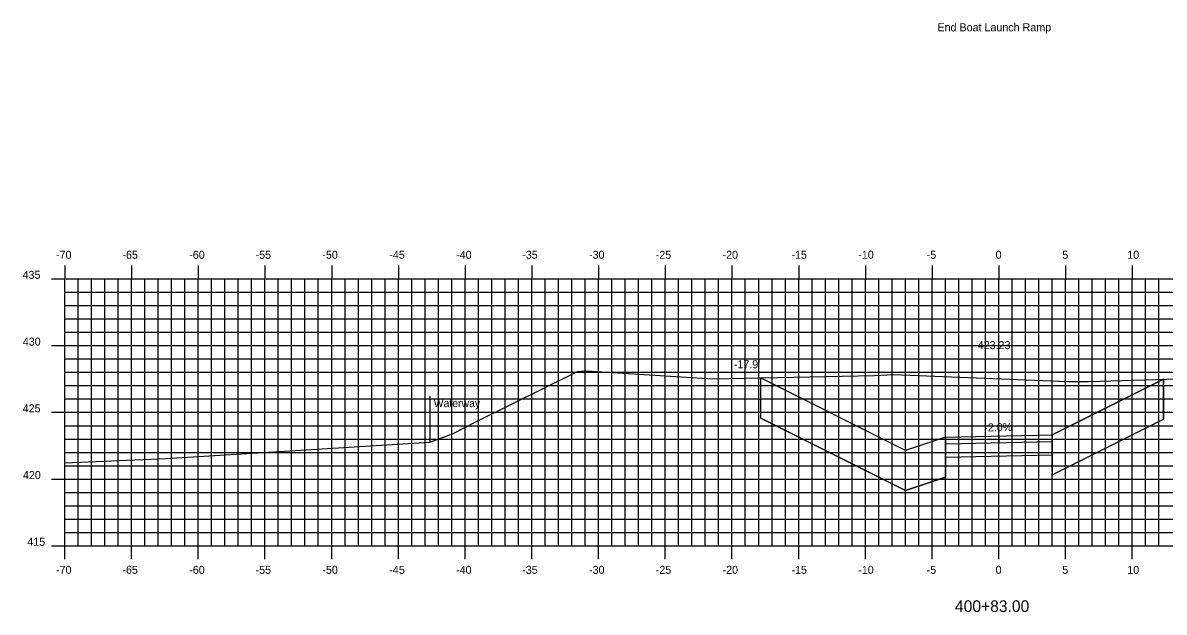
# Model space of a CAD drawing. Extents: x -161 to 764, y 111 to 210.
# Drawn here: x 606.1 to 691.6, y 120.8 to 164.9 of the extents above; entities that cross this region are included whole.
import ezdxf

# ---------------------------------------------------------------- set-up
doc = ezdxf.new("R2010")
doc.units = 0
for name, color, linetype in [('D_Property_Walkway_Paved', 7, 'Continuous'), ('D_Roadway_Centerline_Text', 7, 'Continuous'), ('D_Roadway_SubGrade', 7, 'Continuous'), ('D_Slope_Cut', 7, 'Continuous'), ('D_Text_Standard', 7, 'Continuous'), ('Default', 7, 'Continuous'), ('H_V ANNOTATION', 7, 'Continuous'), ('MAJOR', 7, 'Continuous'), ('MINOR', 7, 'Continuous'), ('PATTERNING', 7, 'Continuous'), ('S_Drainage_Waterway', 7, 'Continuous'), ('S_Roadway_Centerline', 7, 'Continuous')]:
    doc.layers.add(name, color=color, linetype=linetype)

msp = doc.modelspace()

# ---------------------------------------------------------------- linework, layer by layer
at = {"layer": 'D_Property_Walkway_Paved'}
for p, q in [((675.219, 133.914), (675.219, 133.414)), ((683.219, 133.574), (683.219, 134.074))]:
    msp.add_line(p, q, dxfattribs=at)
for points in [[(675.219, 133.914), (683.219, 134.074)], [(675.219, 133.414), (683.219, 133.574)]]:
    msp.add_lwpolyline(points, dxfattribs=at)
at = {"layer": 'D_Roadway_SubGrade'}
msp.add_line((683.219, 132.574), (683.219, 133.574), dxfattribs=at)
msp.add_lwpolyline([(675.219, 133.414), (675.219, 132.414), (683.219, 132.574)], dxfattribs=at)
at = {"layer": 'D_Slope_Cut'}
for p, q in [((661.367, 138.34), (661.356, 135.34)), ((672.219, 132.914), (661.367, 138.34)), ((683.219, 134.074), (691.553, 138.241)), ((691.553, 138.241), (691.566, 135.248)), ((675.219, 133.914), (672.219, 132.914)), ((675.219, 133.914), (675.219, 130.914))]:
    msp.add_line(p, q, dxfattribs=at)
for points in [[(675.219, 130.914), (672.219, 129.914), (661.356, 135.338)], [(683.219, 134.074), (683.219, 131.074), (691.566, 135.248)]]:
    msp.add_lwpolyline(points, dxfattribs=at)
at = {"layer": 'Default'}
msp.add_line((679.219, 133.994), (679.219, 133.494), dxfattribs=at)
at = {"layer": 'MAJOR'}
for p, q in [((609.219, 146.766), (609.219, 145.764)), ((614.219, 146.766), (614.219, 145.764)), ((619.219, 146.766), (619.219, 145.764)), ((624.219, 146.766), (624.219, 145.764)), ((629.219, 146.766), (629.219, 145.764)), ((634.219, 146.766), (634.219, 145.764)), ((639.219, 146.766), (639.219, 145.764)), ((644.219, 146.766), (644.219, 145.764)), ((649.219, 146.766), (649.219, 145.764)), ((654.219, 146.766), (654.219, 145.764)), ((659.219, 146.766), (659.219, 145.764)), ((664.219, 146.766), (664.219, 145.764)), ((669.219, 146.766), (669.219, 145.764)), ((674.219, 146.766), (674.219, 145.764)), ((679.219, 146.766), (679.219, 145.764)), ((684.219, 146.766), (684.219, 145.764)), ((689.219, 146.766), (689.219, 145.764)), ((608.217, 145.764), (609.219, 145.764)), ((609.219, 145.764), (749.219, 145.764)), ((609.219, 125.764), (609.219, 145.764)), ((609.219, 125.764), (609.219, 145.764)), ((609.219, 145.764), (749.219, 145.764)), ((614.219, 125.764), (614.219, 145.764)), ((619.219, 125.764), (619.219, 145.764)), ((624.219, 125.764), (624.219, 145.764)), ((629.219, 125.764), (629.219, 145.764)), ((634.219, 125.764), (634.219, 145.764)), ((639.219, 125.764), (639.219, 145.764)), ((644.219, 125.764), (644.219, 145.764)), ((649.219, 125.764), (649.219, 145.764)), ((654.219, 125.764), (654.219, 145.764)), ((659.219, 125.764), (659.219, 145.764)), ((664.219, 125.764), (664.219, 145.764)), ((669.219, 125.764), (669.219, 145.764)), ((674.219, 125.764), (674.219, 145.764)), ((679.219, 125.764), (679.219, 145.764)), ((684.219, 125.764), (684.219, 145.764)), ((689.219, 125.764), (689.219, 145.764)), ((608.217, 140.764), (609.219, 140.764)), ((609.219, 140.764), (749.219, 140.764)), ((608.217, 135.764), (609.219, 135.764)), ((609.219, 135.764), (749.219, 135.764)), ((608.217, 130.764), (609.219, 130.764)), ((609.219, 130.764), (749.219, 130.764)), ((608.217, 125.764), (609.219, 125.764)), ((609.219, 125.764), (749.219, 125.764)), ((609.219, 125.764), (749.219, 125.764)), ((609.219, 124.762), (609.219, 125.764)), ((614.219, 124.762), (614.219, 125.764)), ((619.219, 124.762), (619.219, 125.764)), ((624.219, 124.762), (624.219, 125.764)), ((629.219, 124.762), (629.219, 125.764)), ((634.219, 124.762), (634.219, 125.764)), ((639.219, 124.762), (639.219, 125.764)), ((644.219, 124.762), (644.219, 125.764)), ((649.219, 124.762), (649.219, 125.764)), ((654.219, 124.762), (654.219, 125.764)), ((659.219, 124.762), (659.219, 125.764)), ((664.219, 124.762), (664.219, 125.764)), ((669.219, 124.762), (669.219, 125.764)), ((674.219, 124.762), (674.219, 125.764)), ((679.219, 124.762), (679.219, 125.764)), ((684.219, 124.762), (684.219, 125.764)), ((689.219, 124.762), (689.219, 125.764))]:
    msp.add_line(p, q, dxfattribs=at)
at = {"layer": 'MINOR'}
for p, q in [((610.219, 125.764), (610.219, 145.764)), ((611.219, 125.764), (611.219, 145.764)), ((612.219, 125.764), (612.219, 145.764)), ((613.219, 125.764), (613.219, 145.764)), ((615.219, 125.764), (615.219, 145.764)), ((616.219, 125.764), (616.219, 145.764)), ((617.219, 125.764), (617.219, 145.764)), ((618.219, 125.764), (618.219, 145.764)), ((620.219, 125.764), (620.219, 145.764)), ((621.219, 125.764), (621.219, 145.764)), ((622.219, 125.764), (622.219, 145.764)), ((623.219, 125.764), (623.219, 145.764)), ((625.219, 125.764), (625.219, 145.764)), ((626.219, 125.764), (626.219, 145.764)), ((627.219, 125.764), (627.219, 145.764)), ((628.219, 125.764), (628.219, 145.764)), ((630.219, 125.764), (630.219, 145.764)), ((631.219, 125.764), (631.219, 145.764)), ((632.219, 125.764), (632.219, 145.764)), ((633.219, 125.764), (633.219, 145.764)), ((635.219, 125.764), (635.219, 145.764)), ((636.219, 125.764), (636.219, 145.764)), ((637.219, 125.764), (637.219, 145.764)), ((638.219, 125.764), (638.219, 145.764)), ((640.219, 125.764), (640.219, 145.764)), ((641.219, 125.764), (641.219, 145.764)), ((642.219, 125.764), (642.219, 145.764)), ((643.219, 125.764), (643.219, 145.764)), ((645.219, 125.764), (645.219, 145.764)), ((646.219, 125.764), (646.219, 145.764)), ((647.219, 125.764), (647.219, 145.764)), ((648.219, 125.764), (648.219, 145.764)), ((650.219, 125.764), (650.219, 145.764)), ((651.219, 125.764), (651.219, 145.764)), ((652.219, 125.764), (652.219, 145.764)), ((653.219, 125.764), (653.219, 145.764)), ((655.219, 125.764), (655.219, 145.764)), ((656.219, 125.764), (656.219, 145.764)), ((657.219, 125.764), (657.219, 145.764)), ((658.219, 125.764), (658.219, 145.764)), ((660.219, 125.764), (660.219, 145.764)), ((661.219, 125.764), (661.219, 145.764)), ((662.219, 125.764), (662.219, 145.764)), ((663.219, 125.764), (663.219, 145.764)), ((665.219, 125.764), (665.219, 145.764)), ((666.219, 125.764), (666.219, 145.764)), ((667.219, 125.764), (667.219, 145.764)), ((668.219, 125.764), (668.219, 145.764)), ((670.219, 125.764), (670.219, 145.764)), ((671.219, 125.764), (671.219, 145.764)), ((672.219, 125.764), (672.219, 145.764)), ((673.219, 125.764), (673.219, 145.764)), ((675.219, 125.764), (675.219, 145.764)), ((676.219, 125.764), (676.219, 145.764)), ((677.219, 125.764), (677.219, 145.764)), ((678.219, 125.764), (678.219, 145.764)), ((680.219, 125.764), (680.219, 145.764)), ((681.219, 125.764), (681.219, 145.764)), ((682.219, 125.764), (682.219, 145.764)), ((683.219, 125.764), (683.219, 145.764)), ((685.219, 125.764), (685.219, 145.764)), ((686.219, 125.764), (686.219, 145.764)), ((687.219, 125.764), (687.219, 145.764)), ((688.219, 125.764), (688.219, 145.764)), ((690.219, 125.764), (690.219, 145.764)), ((691.219, 125.764), (691.219, 145.764)), ((609.219, 144.764), (749.219, 144.764)), ((609.219, 144.764), (610.221, 144.764)), ((609.219, 143.764), (749.219, 143.764)), ((609.219, 143.764), (610.221, 143.764)), ((609.219, 142.764), (749.219, 142.764)), ((609.219, 142.764), (610.221, 142.764)), ((609.219, 141.764), (749.219, 141.764)), ((609.219, 141.764), (610.221, 141.764)), ((609.219, 139.764), (749.219, 139.764)), ((609.219, 139.764), (610.221, 139.764)), ((609.219, 138.764), (749.219, 138.764)), ((609.219, 138.764), (610.221, 138.764)), ((609.219, 137.764), (749.219, 137.764)), ((609.219, 137.764), (610.221, 137.764)), ((609.219, 136.764), (749.219, 136.764)), ((609.219, 136.764), (610.221, 136.764)), ((609.219, 134.764), (749.219, 134.764)), ((609.219, 134.764), (610.221, 134.764)), ((609.219, 133.764), (749.219, 133.764)), ((609.219, 133.764), (610.221, 133.764)), ((609.219, 132.764), (749.219, 132.764)), ((609.219, 132.764), (610.221, 132.764)), ((609.219, 131.764), (749.219, 131.764)), ((609.219, 131.764), (610.221, 131.764)), ((609.219, 129.764), (749.219, 129.764)), ((609.219, 129.764), (610.221, 129.764)), ((609.219, 128.764), (749.219, 128.764)), ((609.219, 128.764), (610.221, 128.764)), ((609.219, 127.764), (749.219, 127.764)), ((609.219, 127.764), (610.221, 127.764)), ((609.219, 126.764), (749.219, 126.764)), ((609.219, 126.764), (610.221, 126.764))]:
    msp.add_line(p, q, dxfattribs=at)
at = {"layer": 'PATTERNING'}
for points in [[(661.367, 138.34), (661.356, 135.34), (672.219, 129.914), (675.219, 130.914), (675.219, 133.914), (672.219, 132.914)], [(683.219, 134.074), (683.219, 131.074), (691.566, 135.248), (691.553, 138.241)]]:
    msp.add_lwpolyline(points, close=True, dxfattribs=at)
at = {"layer": 'S_Drainage_Waterway'}
msp.add_line((636.568, 136.966), (636.568, 133.525), dxfattribs=at)
at = {"layer": 'S_Roadway_Centerline'}
msp.add_lwpolyline([(609.219, 131.987), (616.823, 132.297), (636.568, 133.525), (638.278, 134.155), (640.073, 135.068), (647.652, 138.83), (648.218, 138.879), (648.291, 138.88), (657.792, 138.265), (669.898, 138.518), (671.31, 138.585), (684.384, 138.062), (685.927, 138.075), (701.051, 138.521)], dxfattribs=at)

# ---------------------------------------------------------------- texts
at = {"layer": 'D_Roadway_Centerline_Text'}
for s, p in [('End Boat Launch Ramp', (674.62, 164.307)), ('423.23', (677.633, 140.498))]:
    msp.add_text(s, height=0.6, dxfattribs=at).set_placement(p)
at = {"layer": 'D_Text_Standard'}
msp.add_text("-17.9'", height=0.6, dxfattribs=at).set_placement((659.357, 139.063))
msp.add_text('-2.0%', height=0.6, rotation=1.14576, dxfattribs=at).set_placement((678.135, 134.326))
at = {"layer": 'H_V ANNOTATION'}
for s, height, p in [('-70', 0.6, (608.561, 147.264)), ('-65', 0.6, (613.537, 147.264)), ('-60', 0.6, (618.545, 147.264)), ('-55', 0.6, (623.515, 147.264)), ('-50', 0.6, (628.523, 147.264)), ('-45', 0.6, (633.537, 147.264)), ('-40', 0.6, (638.545, 147.264)), ('-35', 0.6, (643.499, 147.264)), ('-30', 0.6, (648.507, 147.264)), ('-25', 0.6, (653.505, 147.264)), ('-20', 0.6, (658.513, 147.264)), ('-15', 0.6, (663.676, 147.264)), ('-10', 0.6, (668.684, 147.264)), ('-5', 0.6, (673.81, 147.264)), ('0', 0.6, (678.978, 147.264)), ('5', 0.6, (683.97, 147.264)), ('10', 0.6, (688.844, 147.264)), ('435', 0.6, (606.055, 145.764)), ('430', 0.6, (606.071, 140.764)), ('425', 0.6, (606.065, 135.764)), ('420', 0.6, (606.081, 130.764)), ('415', 0.6, (606.408, 125.764)), ('-70', 0.6, (608.561, 123.664)), ('-65', 0.6, (613.537, 123.664)), ('-60', 0.6, (618.545, 123.664)), ('-55', 0.6, (623.515, 123.664)), ('-50', 0.6, (628.523, 123.664)), ('-45', 0.6, (633.537, 123.664)), ('-40', 0.6, (638.545, 123.664)), ('-35', 0.6, (643.499, 123.664)), ('-30', 0.6, (648.507, 123.664)), ('-25', 0.6, (653.505, 123.664)), ('-20', 0.6, (658.513, 123.664)), ('-15', 0.6, (663.676, 123.664)), ('-10', 0.6, (668.684, 123.664)), ('-5', 0.6, (673.81, 123.664)), ('0', 0.6, (678.978, 123.664)), ('5', 0.6, (683.97, 123.664)), ('10', 0.6, (688.844, 123.664)), ('400+83.00', 0.875, (675.934, 120.807))]:
    msp.add_text(s, height=height, rotation=360, dxfattribs=at).set_placement(p)
at = {"layer": 'MAJOR'}
msp.add_text('-', height=1.2588147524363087e-17, rotation=53.1301, dxfattribs=at).set_placement((609.215, 125.764))
at = {"layer": 'S_Drainage_Waterway'}
msp.add_text('Waterway', height=0.585, rotation=360, dxfattribs=at).set_placement((636.865, 136.154))

doc.saveas('drawing.dxf')
